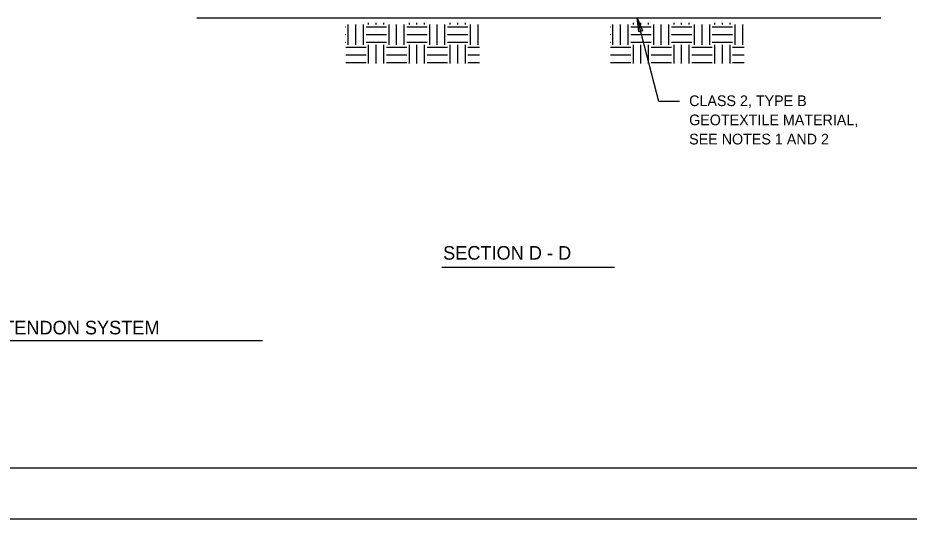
# Model space of a CAD drawing. Extents: x 638850 to 644908, y 297188 to 298900.
# Drawn here: x 641608.6 to 641845.1, y 297277.3 to 297410.3 of the extents above; entities that cross this region are included whole.
import ezdxf

# ---------------------------------------------------------------- set-up
doc = ezdxf.new("R2010")
doc.units = 0
for name, color, linetype in [('1', 7, 'Continuous'), ('13', 7, 'Continuous'), ('3', 7, 'Continuous'), ('4', 7, 'Continuous'), ('6', 7, 'Continuous'), ('8', 7, 'Continuous')]:
    doc.layers.add(name, color=color, linetype=linetype)

msp = doc.modelspace()

# ---------------------------------------------------------------- linework, layer by layer
at = {"layer": '1'}
for p, q in [((642228.96, 297290.84), (641310.96, 297290.84)), ((642242.46, 297277.34), (641270.46, 297277.34))]:
    msp.add_line(p, q, dxfattribs=at)
at = {"layer": '13'}
for p, q in [((641696.27, 297403.12), (641696.27, 297408.52)), ((641698.29, 297403.12), (641698.29, 297408.52)), ((641700.32, 297403.12), (641700.32, 297408.52)), ((641701.67, 297408.52), (641701.67, 297408.89)), ((641703.69, 297408.52), (641703.69, 297408.89)), ((641705.72, 297408.52), (641705.72, 297408.89)), ((641707.07, 297403.12), (641707.07, 297408.52)), ((641709.09, 297403.12), (641709.09, 297408.52)), ((641711.12, 297403.12), (641711.12, 297408.52)), ((641712.47, 297408.52), (641712.47, 297408.89)), ((641714.49, 297408.52), (641714.49, 297408.89)), ((641716.52, 297408.52), (641716.52, 297408.89)), ((641717.87, 297403.12), (641717.87, 297408.52)), ((641719.89, 297403.12), (641719.89, 297408.52)), ((641721.92, 297403.12), (641721.92, 297408.52)), ((641723.27, 297408.52), (641723.27, 297408.89)), ((641725.29, 297408.52), (641725.29, 297408.89)), ((641727.32, 297408.52), (641727.32, 297408.89)), ((641728.67, 297403.12), (641728.67, 297408.52)), ((641730.69, 297403.12), (641730.69, 297408.52)), ((641766.49, 297403.12), (641766.49, 297408.52)), ((641768.51, 297403.12), (641768.51, 297408.52)), ((641770.54, 297403.12), (641770.54, 297408.52)), ((641771.89, 297408.52), (641771.89, 297408.89)), ((641773.91, 297408.52), (641773.91, 297408.89)), ((641775.94, 297408.52), (641775.94, 297408.89)), ((641777.29, 297403.12), (641777.29, 297408.52)), ((641779.31, 297403.12), (641779.31, 297408.52)), ((641781.34, 297403.12), (641781.34, 297408.52)), ((641782.69, 297408.52), (641782.69, 297408.89)), ((641784.71, 297408.52), (641784.71, 297408.89)), ((641786.74, 297408.52), (641786.74, 297408.89)), ((641788.09, 297403.12), (641788.09, 297408.52)), ((641790.11, 297403.12), (641790.11, 297408.52)), ((641792.14, 297403.12), (641792.14, 297408.52)), ((641793.49, 297408.52), (641793.49, 297408.89)), ((641795.51, 297408.52), (641795.51, 297408.89)), ((641797.54, 297408.52), (641797.54, 297408.89)), ((641798.89, 297403.12), (641798.89, 297408.52)), ((641800.91, 297403.12), (641800.91, 297408.52)), ((641695.54, 297407.85), (641695.59, 297407.85)), ((641700.99, 297407.85), (641706.39, 297407.85)), ((641711.79, 297407.85), (641717.19, 297407.85)), ((641722.59, 297407.85), (641727.99, 297407.85)), ((641765.76, 297407.85), (641765.81, 297407.85)), ((641771.21, 297407.85), (641776.61, 297407.85)), ((641782.01, 297407.85), (641787.41, 297407.85)), ((641792.81, 297407.85), (641798.21, 297407.85)), ((641695.54, 297405.82), (641695.59, 297405.82)), ((641695.54, 297403.8), (641695.59, 297403.8)), ((641700.99, 297405.82), (641706.39, 297405.82)), ((641700.99, 297403.8), (641706.39, 297403.8)), ((641711.79, 297405.82), (641717.19, 297405.82)), ((641711.79, 297403.8), (641717.19, 297403.8)), ((641722.59, 297405.82), (641727.99, 297405.82)), ((641722.59, 297403.8), (641727.99, 297403.8)), ((641765.76, 297405.82), (641765.81, 297405.82)), ((641765.76, 297403.8), (641765.81, 297403.8)), ((641771.21, 297405.82), (641776.61, 297405.82)), ((641771.21, 297403.8), (641776.61, 297403.8)), ((641782.01, 297405.82), (641787.41, 297405.82)), ((641782.01, 297403.8), (641787.41, 297403.8)), ((641792.81, 297405.82), (641798.21, 297405.82)), ((641792.81, 297403.8), (641798.21, 297403.8)), ((641695.59, 297402.45), (641700.99, 297402.45)), ((641701.67, 297398.14), (641701.67, 297403.12)), ((641703.69, 297398.14), (641703.69, 297403.12)), ((641705.72, 297398.14), (641705.72, 297403.12)), ((641706.39, 297402.45), (641711.79, 297402.45)), ((641712.47, 297398.14), (641712.47, 297403.12)), ((641714.49, 297398.14), (641714.49, 297403.12)), ((641716.52, 297398.14), (641716.52, 297403.12)), ((641717.19, 297402.45), (641722.59, 297402.45)), ((641723.27, 297398.14), (641723.27, 297403.12)), ((641725.29, 297398.14), (641725.29, 297403.12)), ((641727.32, 297398.14), (641727.32, 297403.12)), ((641727.99, 297402.45), (641731.1, 297402.45)), ((641765.81, 297402.45), (641771.21, 297402.45)), ((641771.89, 297398.14), (641771.89, 297403.12)), ((641773.91, 297398.14), (641773.91, 297403.12)), ((641775.94, 297398.14), (641775.94, 297403.12)), ((641776.61, 297402.45), (641782.01, 297402.45)), ((641782.69, 297398.14), (641782.69, 297403.12)), ((641784.71, 297398.14), (641784.71, 297403.12)), ((641786.74, 297398.14), (641786.74, 297403.12)), ((641787.41, 297402.45), (641792.81, 297402.45)), ((641793.49, 297398.14), (641793.49, 297403.12)), ((641795.51, 297398.14), (641795.51, 297403.12)), ((641797.54, 297398.14), (641797.54, 297403.12)), ((641798.21, 297402.45), (641801.32, 297402.45)), ((641695.59, 297400.42), (641700.99, 297400.42)), ((641706.39, 297400.42), (641711.79, 297400.42)), ((641717.19, 297400.42), (641722.59, 297400.42)), ((641727.99, 297400.42), (641731.1, 297400.42)), ((641765.81, 297400.42), (641771.21, 297400.42)), ((641776.61, 297400.42), (641782.01, 297400.42)), ((641787.41, 297400.42), (641792.81, 297400.42)), ((641798.21, 297400.42), (641801.32, 297400.42)), ((641695.59, 297398.4), (641700.99, 297398.4)), ((641706.39, 297398.4), (641711.79, 297398.4)), ((641717.19, 297398.4), (641722.59, 297398.4)), ((641727.99, 297398.4), (641731.1, 297398.4)), ((641765.81, 297398.4), (641771.21, 297398.4)), ((641776.61, 297398.4), (641782.01, 297398.4)), ((641787.41, 297398.4), (641792.81, 297398.4)), ((641798.21, 297398.4), (641801.32, 297398.4))]:
    msp.add_line(p, q, dxfattribs=at)
at = {"layer": '3'}
for p, q in [((641721.08, 297344.16), (641766.85, 297344.16)), ((641673.47, 297324.58), (641531.06, 297324.58))]:
    msp.add_line(p, q, dxfattribs=at)
at = {"layer": '6'}
for p, q in [((641778.65, 297388.07), (641772.92, 297410.23)), ((641784.12, 297388.07), (641778.65, 297388.07))]:
    msp.add_line(p, q, dxfattribs=at)
msp.add_lwpolyline([(641773.39, 297406.57), (641772.92, 297410.23), (641774.29, 297406.8)], close=True, dxfattribs=at)
at = {"layer": '8'}
msp.add_line((641656.11, 297410.26), (641837.55, 297410.26), dxfattribs=at)

# ---------------------------------------------------------------- texts
at = {"layer": '3'}
for s, p in [('SECTION D - D', (641721.42, 297346.14)), ('TYPICAL RESTRAINT CLIP AND TENDON SYSTEM', (641531.11, 297326.33))]:
    msp.add_text(s, height=3.6022, dxfattribs=at).set_placement(p)
at = {"layer": '4'}
for s, p in [('CLASS 2, TYPE B', (641786.69, 297386.86)), ('GEOTEXTILE MATERIAL,', (641786.69, 297381.78)), ('SEE NOTES 1 AND 2', (641786.69, 297376.69))]:
    msp.add_text(s, height=2.835, dxfattribs=at).set_placement(p)

doc.saveas('drawing.dxf')
